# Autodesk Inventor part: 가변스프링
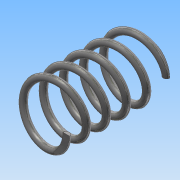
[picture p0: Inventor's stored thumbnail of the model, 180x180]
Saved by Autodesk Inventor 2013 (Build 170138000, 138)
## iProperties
Created: 2018-10
Part Number: 가변스프링
Material: 스테인리스강
Document SubType Name: Modeling
Designer: Administrator
Density: 8.08 g/cm^3
Mass: 6.29087 g
Surface Area: 15.792 cm^2
Volume: 0.778573 cm^3
Author: Administrator
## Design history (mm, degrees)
sketch "스케치1"
  geometry: L1 (0, 0)-(0, 30.5); L2 (0, 0)-(8, 0); L3 (0, 30.5)-(8, 30.5); C1 r 1 at (8, 0)
  constraints: 6 end point, 1 centre point, 1 coincident, 1 parallel, 1 perpendicular, 1 vertical
  dimensions: "d0" = 30.5 distance of L1.start L1.end (derived); "d1" = 2 diameter of C1; "d2" = 16 diameter of L2.end L1
feature "코일1" sketch "스케치1" pitch "d3" = 10; turns "d5" = 5; dims "d4" = 30.5 (= d0), "d6" = 0, angle "d7" = 90 deg, angle "d8" = 90 deg, "d9" = 0, "d10" = 0
sketch "스케치2"
  geometry: L1 (30.5, 10)-(0, 10); L2 (0, 10)-(0, -10); L3 (0, -10)-(30.5, -10); L4 (30.5, -10)-(30.5, 10); 2 further points
  constraints: 8 end point, 2 parallel, 1 coincident, 1 horizontal, 1 midpoint, 1 perpendicular
  dimensions: "d11" = 20 distance of L1.end L2.end; "d13" = 30.5 distance of L2.end L3.end (derived)
extrude "돌출1" sketch "스케치2" stored distance "d14" = 30.5 (= d0); taper "d15" = 0 deg
node "솔리드1"
